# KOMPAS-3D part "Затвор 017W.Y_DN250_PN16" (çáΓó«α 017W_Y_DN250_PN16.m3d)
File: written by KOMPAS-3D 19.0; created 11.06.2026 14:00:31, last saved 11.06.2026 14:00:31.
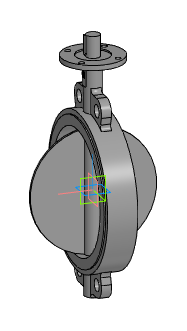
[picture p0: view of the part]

Document properties: Автор: Евгений; Полное имя файла: Z:\3.Личные\kachalov\001_3d для проектировщиков\x.x Тип 017W.Y(S) Затвор дисковый поворотный межфланцевый\_stp_Затвор 017W.Y_DN50-DN350\Затвор 017W_Y_DN250_PN16.m3d

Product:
- Part/product: Затвор 017W.Y_DN250_PN16

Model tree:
1. Операция без истории:1  (labels: Затвор 017W.Y_DN250_PN16)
